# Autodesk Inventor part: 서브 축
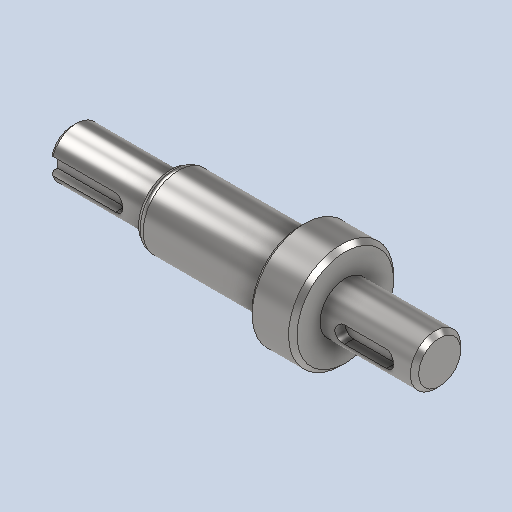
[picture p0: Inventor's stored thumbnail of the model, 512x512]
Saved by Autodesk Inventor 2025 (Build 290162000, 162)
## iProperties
Created: 2024-07
Part Number: 서브 축
Material: 강철, 연강
Document SubType Name: Modeling
Designer: 학생
Density: 7.86 g/cm^3
Appearance: 기본값
Author: jhkim
Revision Number: 1
Sending System: Autodesk Inventor 2025
Preprocessor: ST-DEVELOPER v20
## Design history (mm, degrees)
feature "솔리드1"
node "솔리드2"
